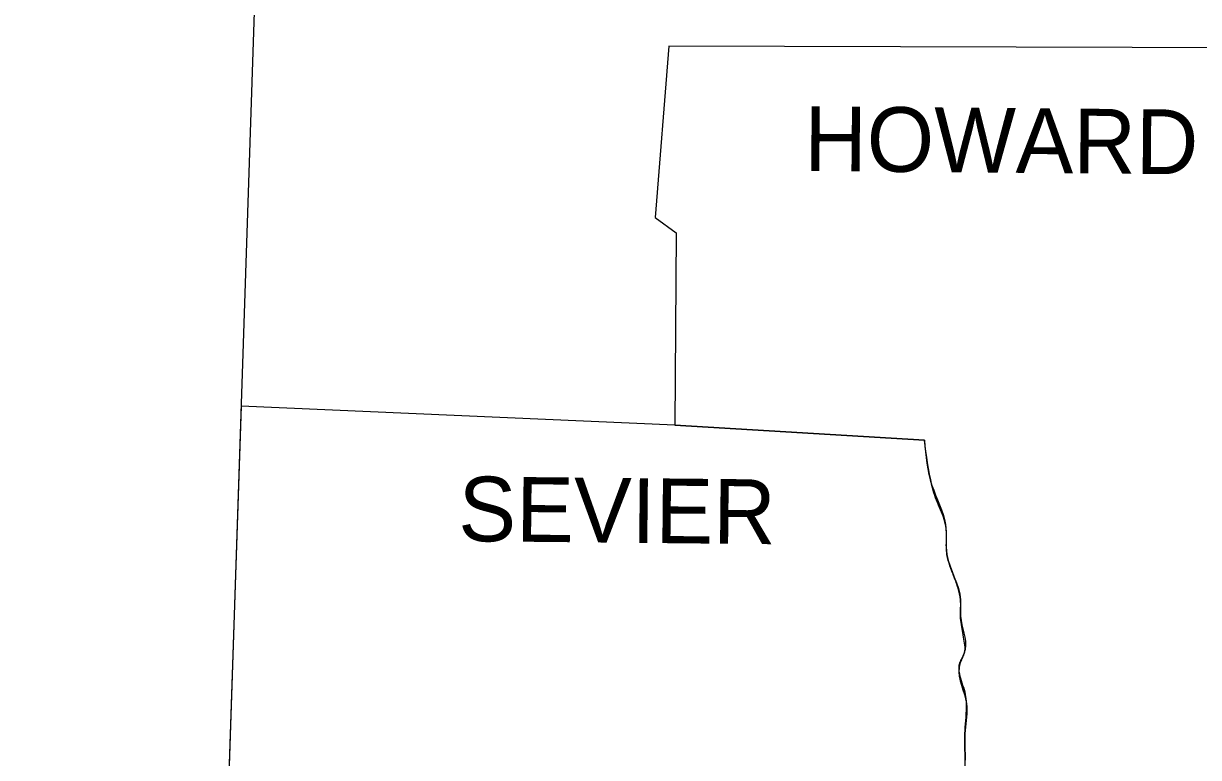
# Model space of a CAD drawing. Extents: x 3046 to 131673, y -8885 to 10756.
# Drawn here: x 63766 to 64530, y 6620 to 7097 of the extents above; entities that cross this region are included whole.
import ezdxf

# ---------------------------------------------------------------- set-up
doc = ezdxf.new("R2010")
doc.units = 0
for name, color, linetype in [('1', 7, 'Continuous'), ('2', 7, 'Continuous'), ('R_Annotation', 7, 'Continuous')]:
    doc.layers.add(name, color=color, linetype=linetype)

msp = doc.modelspace()

# ---------------------------------------------------------------- linework, layer by layer
at = {"layer": '1'}
for points in [[(63766.12484423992, 10312.988270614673), (63968.6550556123, 8686.876140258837), (63880.59844191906, 6032.458444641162)], [(64849.22119109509, 8257.35554737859), (64847.264377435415, 7684.987559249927), (64798.34403670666, 7684.009152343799), (64802.25766383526, 7654.656947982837), (64755.294136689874, 7655.635354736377), (64754.315729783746, 7634.110404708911), (64708.3306093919, 7634.110404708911), (64709.30901629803, 7618.455895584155), (64640.820538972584, 7616.499081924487), (64639.842132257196, 7556.816266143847), (64573.31046859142, 7562.686707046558), (64562.54799369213, 7081.31055302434), (64185.861368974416, 7082.2889597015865), (64177.05570769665, 6970.7505825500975), (64190.753402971, 6960.966514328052), (64189.774996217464, 6835.7304417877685), (63907.6845344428, 6848.130022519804)], [(64189.774996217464, 6835.7304417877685), (64352.190527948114, 6825.946373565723)]]:
    msp.add_lwpolyline(points, dxfattribs=at)
msp.add_spline([(64352.190527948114, 6825.946373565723), (64357.08256194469, 6796.594169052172), (64365.8882234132, 6771.155591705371), (64366.86663012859, 6751.587455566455), (64375.6722915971, 6722.2352509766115), (64375.6722915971, 6711.472775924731), (64378.607512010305, 6689.947825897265), (64374.69388469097, 6678.2069442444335), (64379.585918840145, 6654.7251806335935), (64378.607512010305, 6637.11385784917), (64378.607512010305, 6622.437755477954), (64379.585918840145, 6597.977585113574), (64387.41317324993, 6576.452635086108), (64395.24042777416, 6544.16521015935), (64400.13246199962, 6527.532294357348), (64407.95971652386, 6502.09371708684), (64412.851750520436, 6470.7846988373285), (64413.830157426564, 6447.302935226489), (64411.87334380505, 6425.777985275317), (64417.7437847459, 6401.317814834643), (64428.5062596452, 6376.857644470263), (64442.203955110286, 6353.375880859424), (64458.83687095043, 6326.9588968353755), (64470.57775275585, 6306.41235356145), (64485.25385512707, 6283.908996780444), (64496.99473693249, 6265.319267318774), (64514.606059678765, 6241.837503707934), (64522.433314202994, 6222.2693672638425), (64522.433314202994, 6194.873976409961), (64526.3469413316, 6169.435399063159), (64525.368534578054, 6141.061601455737), (64523.41172095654, 6115.623024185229), (64516.56287330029, 6080.400378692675), (64521.454907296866, 6063.767462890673), (64540.04463679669, 6039.307292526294), (64551.785518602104, 6032.458444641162), (64572.33206187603, 6028.544817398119), (64582.11613005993, 6014.847121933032), (64587.98657096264, 5994.300578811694), (64608.53311408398, 5987.451731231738), (64631.03647082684, 5985.49491757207), (64641.79894587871, 5973.75403576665), (64656.475048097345, 5958.099526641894), (64661.36708228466, 5950.272272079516)], degree=3, dxfattribs=at)
at = {"layer": 'R_Annotation'}
for p, q in [((63907.657241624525, 6848.1309279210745), (63894.80040004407, 6460.56858172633)), ((64189.774996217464, 6835.7304417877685), (63907.6845344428, 6848.130022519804)), ((64352.190527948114, 6825.946373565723), (64189.774996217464, 6835.7304417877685))]:
    msp.add_line(p, q, dxfattribs=at)
msp.add_lwpolyline([(63907.6845344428, 6848.130022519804), (63907.657241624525, 6848.1309279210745)], dxfattribs=at)
msp.add_spline([(64447.58236607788, 6344.817790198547), (64442.203955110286, 6353.375880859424), (64428.5062596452, 6376.857644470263), (64417.7437847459, 6401.317814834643), (64411.87334380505, 6425.777985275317), (64412.030355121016, 6431.153156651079), (64412.73305342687, 6436.531106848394), (64413.495100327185, 6441.913733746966), (64413.830157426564, 6447.302935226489), (64412.851750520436, 6470.7846988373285), (64407.95971652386, 6502.09371708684), (64400.13246199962, 6527.532294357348), (64395.24042777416, 6544.16521015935), (64391.21186765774, 6560.285411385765), (64387.41317324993, 6576.452635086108), (64385.517164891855, 6581.856962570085), (64383.135167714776, 6587.125003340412), (64380.935359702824, 6592.438097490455), (64379.585918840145, 6597.977585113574), (64379.01840292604, 6604.086760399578), (64378.74080657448, 6610.200866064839), (64378.607512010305, 6622.437755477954), (64378.607512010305, 6637.11385784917), (64379.585918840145, 6654.7251806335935), (64378.94016426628, 6660.668917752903), (64377.273513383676, 6666.550356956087), (64375.54005669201, 6672.389648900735), (64374.69388469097, 6678.2069442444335), (64375.30526026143, 6681.1594562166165), (64376.69395418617, 6684.059387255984), (64378.06102019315, 6686.9683172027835), (64378.607512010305, 6689.947825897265), (64378.073936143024, 6695.294480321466), (64377.16843101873, 6700.6712627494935), (64376.2486612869, 6706.067564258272), (64375.6722915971, 6711.472775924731), (64375.6722915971, 6722.2352509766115), (64374.08645665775, 6729.695935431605), (64371.50804037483, 6736.974418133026), (64368.81033433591, 6744.221368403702), (64366.86663012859, 6751.587455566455), (64366.45190580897, 6756.44084233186), (64366.49472160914, 6761.380806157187), (64366.4788899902, 6766.31612872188), (64365.8882234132, 6771.155591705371), (64363.94163622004, 6777.571737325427), (64361.406384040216, 6783.843571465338), (64358.91063617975, 6790.131060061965), (64357.08256194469, 6796.594169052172), (64352.190527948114, 6825.946373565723)], degree=3, dxfattribs=at)

# ---------------------------------------------------------------- texts
at = {"layer": '2'}
for s, height, rotation, p in [('HOWARD', 42.07344995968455, 359.51445555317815, (64273.91798247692, 7001.081193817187)), ('SEVIER', 42.0734499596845, 359.42706112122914, (64048.88441455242, 6760.393116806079))]:
    msp.add_text(s, height=height, rotation=rotation, dxfattribs=at).set_placement(p)

doc.saveas('drawing.dxf')
